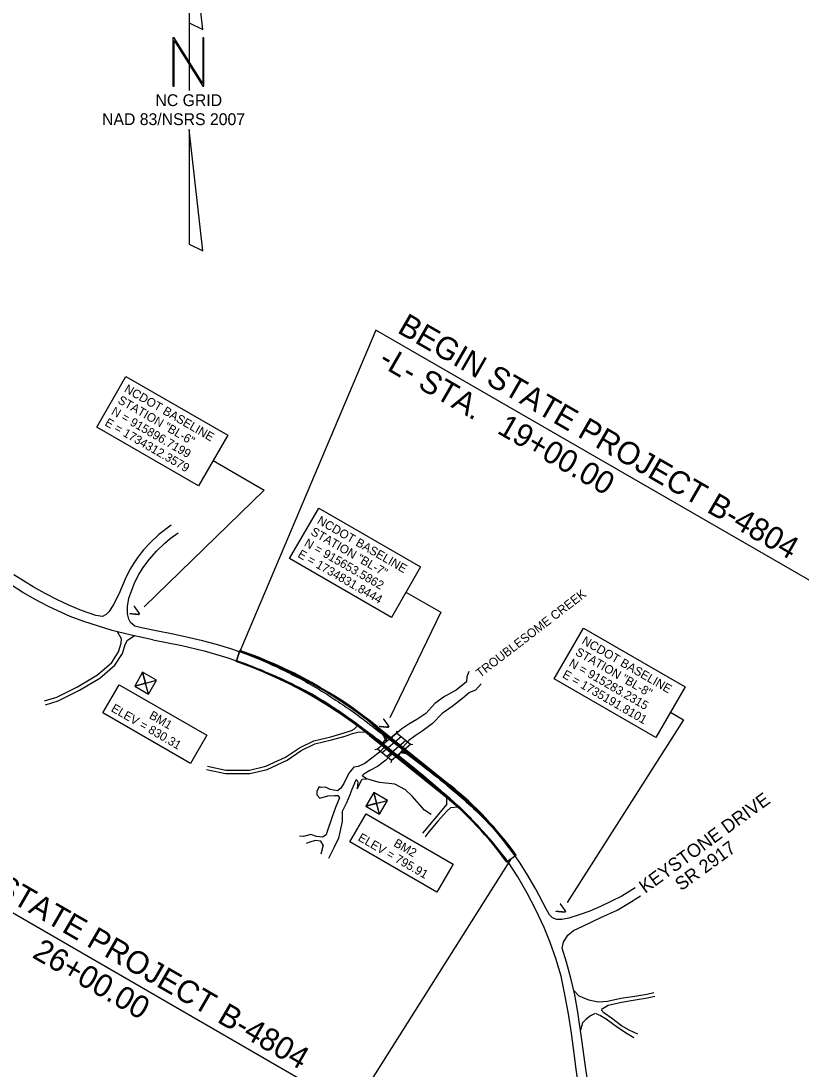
# Model space of a CAD drawing. Extents: x 1729269 to 1736953, y 913137 to 919486.
# Drawn here: x 1734090 to 1735676, y 914972 to 917102 of the extents above; entities that cross this region are included whole.
import ezdxf

# ---------------------------------------------------------------- set-up
doc = ezdxf.new("R2010")
doc.units = 0
for name, color, linetype in [('CTL North Arrow NAD 83 NSRS 2007 CELL', 7, 'Continuous'), ('CTL Sheet Text', 7, 'Continuous'), ('Default', 7, 'Continuous'), ('Exist Hydro Stream or Body of Water', 7, 'Continuous'), ('Exist Roads EOP', 7, 'Continuous'), ('Exist Roads Soil', 7, 'Continuous'), ('Exist Structure Major Deck Tunnel Box Culvert', 7, 'Continuous'), ('Old_Level_3', 7, 'Continuous'), ('Old_Level_57', 7, 'Continuous'), ('Proposed Right of Way Monument PSD Text', 7, 'Continuous')]:
    doc.layers.add(name, color=color, linetype=linetype)

# ---------------------------------------------------------------- blocks, each defined once
blk = doc.blocks.new('CTL NORTH ARROW NAD 83 NSRS 2007')
at = {"layer": 'Default'}
blk.add_line((0, 0), (0, 0), dxfattribs=at)
for points in [[(-0.003, 1.746), (-0.003, 0.579), (0.135, 0.511)], [(-0.168, -0.065), (-0.154, -0.065), (-0.154, 0.401), (0.135, -0.065), (0.148, -0.065), (0.148, 0.428), (0.135, 0.428), (0.135, -0.038), (-0.154, 0.428), (-0.168, 0.428)], [(-0.003, -1.671), (0.135, -1.739), (-0.003, -0.505)]]:
    blk.add_lwpolyline(points, close=True, dxfattribs=at)
blk.add_lwpolyline([(-0.003, 0.579), (-0.003, -0.107)], dxfattribs=at)
for s, p in [('NC GRID', (-0.345, -0.267)), ('NAD 83/NSRS 2007', (-0.888, -0.46))]:
    blk.add_text(s, height=0.12, dxfattribs=at).set_placement(p)

msp = doc.modelspace()

# ---------------------------------------------------------------- linework, layer by layer
at = {"layer": 'CTL Sheet Text'}
for p, q in [((1734811.2, 916473.9), (1734530.8, 915811.4)), ((1735762.6, 915924.6), (1734811.2, 916473.9)), ((1734764.2, 914889.5), (1733866.3, 915408)), ((1734764.2, 914889.5), (1735086.8, 915399.5))]:
    msp.add_line(p, q, dxfattribs=at)
at = {"layer": 'Default'}
for p, q in [((1734534, 915820.9), (1734527.5, 915801.9)), ((1734527.5, 915801.9), (1734534, 915820.9)), ((1734534, 915820.9), (1734534.7, 915822.7)), ((1734526.9, 915800.1), (1734527.5, 915801.9)), ((1734812.3, 915666.9), (1734960.6, 915547.4)), ((1734812.3, 915666.9), (1734960.6, 915547.4)), ((1734813.6, 915668.4), (1734961.9, 915549)), ((1734798.5, 915649.7), (1734946.8, 915530.3)), ((1734948.1, 915531.8), (1734799.8, 915651.3)), ((1734799.8, 915651.3), (1734948.1, 915531.8)), ((1734853, 915654.7), (1734814.6, 915621.9)), ((1734862.6, 915647), (1734824.1, 915614.3)), ((1734865.8, 915621.1), (1734834.2, 915645.7)), ((1734853, 915654.7), (1734854.2, 915659.3)), ((1734881.6, 915631.7), (1734853, 915654.7)), ((1734814.6, 915621.9), (1734809, 915621)), ((1734843.2, 915599), (1734814.6, 915621.9)), ((1734872.1, 915639.4), (1734833.6, 915606.6)), ((1734881.6, 915631.7), (1734843.2, 915599)), ((1734881.6, 915631.7), (1734886, 915632.5)), ((1734843.2, 915599), (1734841.5, 915594.5)), ((1735094.9, 915405.3), (1735078.7, 915393.7)), ((1735094.9, 915405.3), (1735078.7, 915393.7)), ((1735096.6, 915406.5), (1735094.9, 915405.3)), ((1735077.1, 915392.5), (1735078.7, 915393.7))]:
    msp.add_line(p, q, dxfattribs=at)
for points in [[(1734302.9, 916379.7), (1734509.9, 916260.2), (1734450.5, 916157.3), (1734243.5, 916276.9)], [(1734695, 916112.2), (1734902, 915992.7), (1734842.6, 915889.8), (1734635.6, 916009.3)], [(1735233.1, 915867.8), (1735439.7, 915748.5), (1735380.3, 915645.6), (1735173.7, 915764.9)], [(1734289.3, 915753.1), (1734467.5, 915650.3), (1734434.5, 915593.1), (1734256.3, 915696)], [(1734831.4, 915649), (1734832.9, 915637.5), (1734827.6, 915647.8), (1734829.9, 915647)], [(1734872.8, 915612.7), (1734861.4, 915614.5), (1734872.8, 915616.7), (1734871.4, 915614.7)], [(1734791.2, 915490.5), (1734968.2, 915388.4), (1734935.2, 915331.2), (1734758.2, 915433.4)]]:
    msp.add_lwpolyline(points, close=True, dxfattribs=at)
for points in [[(1734480.2, 916208.8), (1734584, 916148.8), (1734339.8, 915911.5)], [(1734872.3, 915941.3), (1734943.4, 915900.3), (1734839.3, 915685.7)], [(1735410, 915697), (1735436.7, 915681.6), (1735200.2, 915310.2)], [(1734865.8, 915621.1), (1734856.1, 915608.7), (1734824.7, 915633.5), (1734834.2, 915645.7)]]:
    msp.add_lwpolyline(points, dxfattribs=at)
for centre, radius, start, end in [((1734232, 914946.5), 925, 51.1452, 70.9432), ((1734232, 914946.5), 925, 51.1452, 70.9432), ((1734232, 914946.5), 927, 51.1452, 70.9432), ((1734232, 914946.5), 903, 51.1452, 70.9432), ((1734232, 914946.5), 905, 51.1452, 70.9432), ((1734232, 914946.5), 905, 51.1452, 70.9432), ((1734505.8, 914982.8), 725, 35.6458, 51.1452), ((1734505.8, 914982.8), 725, 35.6458, 51.1452), ((1734505.8, 914982.8), 727, 35.6458, 51.1452), ((1734505.8, 914982.8), 703, 35.6458, 51.1452), ((1734505.8, 914982.8), 705, 35.6458, 51.1452), ((1734505.8, 914982.8), 705, 35.6458, 51.1452)]:
    msp.add_arc(centre, radius, start, end, dxfattribs=at)
at = {"layer": 'Exist Hydro Stream or Body of Water'}
for points in [[(1735000.4, 915780.1), (1734996.3, 915769.1), (1734995.1, 915758.7), (1734974.1, 915741.8), (1734950.8, 915729), (1734930.8, 915714.9), (1734912.7, 915694.7), (1734894.6, 915682.3), (1734878, 915673.1), (1734864, 915663.1), (1734844.1, 915646.3), (1734840.1, 915641.3)], [(1735025.5, 915755.1), (1735013.8, 915742.3), (1735001.7, 915737.1), (1734987.9, 915725.5), (1734966.5, 915708.8), (1734946.2, 915694.3), (1734926.1, 915674.1), (1734907.3, 915660), (1734890.9, 915649), (1734878.2, 915640), (1734865.9, 915626), (1734862.5, 915623.7)], [(1734829.7, 915627.7), (1734818.6, 915616.3), (1734803.2, 915603.5), (1734789, 915592.7), (1734774.9, 915586.9), (1734766.1, 915585.3), (1734756.4, 915573.1), (1734745.7, 915552.1), (1734739.4, 915542.1)], [(1734847.9, 915613.6), (1734841.1, 915608.9), (1734831.2, 915599.4), (1734814.7, 915587.1), (1734798.9, 915578.8), (1734786.7, 915571.3), (1734783.1, 915567.8)], [(1734772.4, 915559.9), (1734769.7, 915557.9), (1734762.5, 915540.3), (1734758.5, 915529.5), (1734751.2, 915513.2), (1734742.9, 915495.6), (1734742.8, 915475.1), (1734735, 915441.4), (1734725.8, 915421.7), (1734715.1, 915399.6)], [(1734772.4, 915559.9), (1734774.2, 915556), (1734772.9, 915541.2), (1734783.4, 915561.2), (1734792.4, 915561.8), (1734783.1, 915567.8)], [(1734909.8, 915498.1), (1734884.9, 915526.8), (1734871.6, 915539.2), (1734849.9, 915550.9), (1734818.6, 915554.5), (1734792.4, 915561.8)], [(1734739.4, 915542.1), (1734732.8, 915537.7), (1734718.5, 915540.1), (1734709, 915544.8), (1734699.7, 915544.4), (1734696, 915545.5), (1734691.3, 915536.4), (1734691.4, 915529.3), (1734696.9, 915522.3), (1734713.4, 915527.1), (1734726.7, 915527.7), (1734733.8, 915527.9), (1734736.9, 915522.9)], [(1734736.9, 915523.3), (1734736.9, 915522.9), (1734729.3, 915503.3), (1734722.6, 915484.3), (1734711.2, 915452.5), (1734709.8, 915448)], [(1734923.6, 915489), (1734909.8, 915498.1)], [(1734709.8, 915448), (1734702.9, 915442.9), (1734690.2, 915444.4), (1734679.2, 915448.4), (1734664.3, 915444.6), (1734655.6, 915445.4)], [(1734703.8, 915426.7), (1734699.1, 915434.9), (1734687.5, 915436.3), (1734676.6, 915433.2), (1734669.1, 915430.6)], [(1734703.8, 915426.7), (1734699.1, 915408.7)]]:
    msp.add_lwpolyline(points, dxfattribs=at)
at = {"layer": 'Exist Roads EOP'}
for points in [[(1734394.7, 916077.1), (1734369.9, 916058.3), (1734352, 916041.7), (1734338.9, 916027.2), (1734327.3, 916012.3), (1734318.9, 916000.2), (1734311, 915987.6), (1734301.1, 915967.3), (1734288.4, 915937.1), (1734278, 915916.2), (1734269.2, 915901.9), (1734263.1, 915896.1), (1734255.2, 915892), (1734241.7, 915894), (1734212.5, 915904), (1734187.1, 915914.6), (1734163.6, 915925.7), (1734138.6, 915938.5), (1734114.2, 915952), (1734094.4, 915963.9), (1734074.8, 915976.6)], [(1734357.9, 915844.5), (1734311, 915854.6), (1734275.3, 915863.4), (1734247.5, 915872), (1734217.2, 915881.5), (1734189.8, 915891.8), (1734164.5, 915903.1), (1734143.9, 915913), (1734120.1, 915925.3), (1734093.2, 915940.8), (1734068, 915956.5), (1734040.6, 915976.2), (1734015.8, 915995.2), (1733991.1, 916015.8), (1733969, 916035.9), (1733954, 916050.6), (1733941.6, 916063.3)], [(1734367.8, 915861.9), (1734334.4, 915868.6), (1734321.3, 915872.1), (1734312.5, 915879.3), (1734309, 915886.6), (1734306.5, 915897.4), (1734306.4, 915912.3), (1734309.2, 915929.3), (1734314.9, 915945.5), (1734321, 915961.8), (1734328.9, 915976.9), (1734338, 915991), (1734350.9, 916008.6), (1734365.8, 916025), (1734381.9, 916040.7), (1734393.1, 916050.5), (1734409.2, 916061.5)], [(1734806.6, 915670.5), (1734794.2, 915681), (1734768.3, 915699.8), (1734740.3, 915718.7), (1734708.5, 915739.1), (1734678.6, 915756.5), (1734644.4, 915773.4), (1734606.7, 915791.5), (1734576.2, 915804.2), (1734547.7, 915815.2), (1734516.3, 915826.2), (1734487.1, 915834.9), (1734458.4, 915842.5), (1734423.7, 915850.6), (1734395.8, 915856.4), (1734367.8, 915861.9)], [(1734357.9, 915844.5), (1734416.4, 915832.9), (1734461.9, 915821.8), (1734507.9, 915808.5), (1734539.6, 915797.8), (1734580.6, 915781.2), (1734628, 915760.4), (1734664.3, 915740.2), (1734703.6, 915717.9), (1734746.1, 915690.1), (1734777, 915667.9)], [(1734777, 915667.9), (1734823.7, 915632.9)], [(1734806.6, 915670.5), (1734823.8, 915654.7), (1734834, 915645.7)], [(1734866.7, 915620.1), (1734865.5, 915621)], [(1735092, 915407.8), (1735070.9, 915436.3), (1735050.3, 915461.3), (1735020.8, 915492), (1734998.4, 915513.9), (1734970.6, 915538.4), (1734932.1, 915569.9), (1734898.2, 915597.2), (1734866.7, 915620.1)], [(1734944.8, 915533.6), (1734856.3, 915608.2)], [(1734944.8, 915533.6), (1734977.7, 915504.8), (1735009.1, 915475.9), (1735029.4, 915454.3), (1735050.5, 915429.9), (1735075.9, 915397.9)], [(1735338, 915340.4), (1735310.9, 915323.6), (1735288.9, 915312.4), (1735268.1, 915302.2), (1735246.3, 915292.5), (1735224.1, 915285), (1735203.5, 915278.4), (1735188.9, 915275.6), (1735179.1, 915275.8), (1735170.3, 915279.5), (1735164.1, 915285.3), (1735157.3, 915297.4), (1735136.6, 915337.4), (1735118, 915368.6), (1735102.9, 915392.3), (1735092, 915407.8)], [(1735242.5, 914819.2), (1735236, 914850.6), (1735229.7, 914892.9), (1735224.3, 914929.5), (1735218.2, 914971.6), (1735214, 915003.7), (1735208.6, 915044.9), (1735202.9, 915083.8), (1735195.5, 915123.4), (1735187.7, 915160.5), (1735177.1, 915196.8), (1735165.8, 915229.4), (1735153.3, 915259.8), (1735135.8, 915296.9), (1735118.8, 915329.6), (1735099.9, 915362.6), (1735080.5, 915391.6), (1735075.9, 915397.9)], [(1735190.1, 915217.8), (1735192.4, 915229.9), (1735201.2, 915244), (1735212.7, 915253.7), (1735232, 915262.2), (1735268.8, 915279.7), (1735301.6, 915294.7), (1735325.5, 915308.7), (1735349.4, 915324)], [(1735260.6, 914824.7), (1735254.7, 914857), (1735249.1, 914892.7), (1735242.4, 914939.7), (1735236, 914986.4), (1735230.7, 915026.7), (1735221.6, 915087.2), (1735215.3, 915122.6), (1735207.4, 915156.6), (1735198.8, 915189.4), (1735190.1, 915217.8)]]:
    msp.add_lwpolyline(points, dxfattribs=at)
at = {"layer": 'Exist Roads Soil'}
for points in [[(1734293.4, 915837.2), (1734294, 915846.6), (1734285.6, 915860.8)], [(1734301.2, 915834.9), (1734306.1, 915843.6), (1734319.7, 915852.7)], [(1734137.1, 915720), (1734162.2, 915728), (1734204.8, 915749), (1734245, 915773.2), (1734274, 915798.4), (1734288.2, 915819.9), (1734293.4, 915837.2)], [(1734139.5, 915712.2), (1734165.3, 915720.4), (1734208.8, 915741.8), (1734249.8, 915766.5), (1734280.2, 915792.9), (1734295.7, 915816.4), (1734301.2, 915834.9)], [(1734761.5, 915660.2), (1734767.6, 915663.5), (1734773.5, 915669.8)], [(1734467.1, 915580.6), (1734505.7, 915572.8), (1734554.7, 915572.6), (1734589.9, 915580.8), (1734630.6, 915599.8), (1734659.3, 915619.1), (1734687.1, 915632.8), (1734721.1, 915640.7), (1734748.8, 915648.7), (1734763.7, 915653.9)], [(1734468.5, 915587.2), (1734506.4, 915579.5), (1734553.9, 915579.3), (1734587.7, 915587.2), (1734627.3, 915605.6), (1734655.9, 915624.9), (1734684.8, 915639.2), (1734719.4, 915647.2), (1734746.8, 915655.1), (1734761.5, 915660.2)], [(1734763.7, 915653.9), (1734774.7, 915656.9), (1734789.8, 915657.6)], [(1734955.7, 915510.2), (1734955.7, 915518), (1734955.3, 915524.4)], [(1734955.7, 915510.2), (1734930.8, 915481), (1734909.7, 915455.9), (1734905.9, 915451)], [(1734955.2, 915496.3), (1734937.4, 915475.5), (1734916.4, 915450.5), (1734911, 915443.7)], [(1734955.2, 915496.3), (1734963.6, 915503.2), (1734977.8, 915504.7)], [(1735281.8, 915108.9), (1735263.1, 915107.9), (1735244.4, 915112), (1735230.9, 915117.6), (1735224.4, 915120.3), (1735213.1, 915131.9)], [(1735376.3, 915126.7), (1735362, 915123.2), (1735337.3, 915119.5), (1735309, 915115), (1735281.8, 915108.9)], [(1735378.1, 915119.1), (1735363.5, 915115.6), (1735338.5, 915111.8), (1735310.4, 915107.3), (1735283.5, 915101.3)], [(1735343.5, 915042.8), (1735326.3, 915050.8), (1735310.7, 915059.7), (1735290.2, 915075), (1735274.9, 915086), (1735269, 915092.1)], [(1735283.5, 915101.3), (1735269.6, 915092.6)], [(1735256.8, 915085.1), (1735247.7, 915079.8), (1735237.8, 915072.8), (1735231, 915065.8), (1735227.1, 915050.9)], [(1735258.2, 915084.5), (1735267.8, 915080.5), (1735279.3, 915074), (1735302.1, 915057.1), (1735322, 915043.9), (1735335.9, 915035.8)]]:
    msp.add_lwpolyline(points, dxfattribs=at)
at = {"layer": 'Exist Structure Major Deck Tunnel Box Culvert'}
msp.add_lwpolyline([(1734855.7, 915607.7), (1734823.4, 915632.5), (1734834.2, 915646), (1734865.6, 915621.3), (1734855.7, 915607.7)], dxfattribs=at)
at = {"layer": 'Old_Level_3'}
for points in [[(1734543.6, 915817), (1734596.7, 915795.1), (1734643.1, 915772.7), (1734683.1, 915750.9), (1734729.8, 915721.6), (1734764.7, 915698), (1734803.6, 915668.7), (1734832.5, 915645.7)], [(1734549.9, 915794.3), (1734589.6, 915778.2), (1734633.6, 915758.4), (1734673.1, 915738.4), (1734721.2, 915709.8), (1734758.5, 915684.1), (1734794.6, 915657.6), (1734825.3, 915634.6)], [(1734865.8, 915619.4), (1734899.8, 915592.9), (1734931, 915568.7), (1734948.4, 915554.7), (1734979.8, 915528.3), (1735019.6, 915492), (1735051.5, 915459.1), (1735067.6, 915441.5)], [(1734865.8, 915619.4), (1734899.8, 915592.9), (1734931, 915568.7), (1734948.4, 915554.7), (1734979.8, 915528.3), (1735019.6, 915492), (1735051.5, 915459.1), (1735067.6, 915441.5)], [(1734858, 915608.9), (1734899.1, 915575.6), (1734937, 915543.4), (1734973.3, 915511.8), (1735003.9, 915482.3)], [(1734858, 915608.9), (1734899.1, 915575.6), (1734937, 915543.4), (1734973.3, 915511.8), (1735003.9, 915482.3)]]:
    msp.add_spline(points, degree=3, dxfattribs=at)
at = {"layer": 'Old_Level_57'}
for p, q in [((1734348.9, 915734), (1734337, 915778.3)), ((1734320.8, 915750.2), (1734365.1, 915762.1)), ((1734818.5, 915489.9), (1734806.7, 915534.2)), ((1734790.4, 915506.1), (1734834.7, 915518))]:
    msp.add_line(p, q, dxfattribs=at)
for points in [[(1734365.1, 915762.1), (1734337, 915778.3), (1734320.8, 915750.2), (1734348.9, 915734)], [(1734834.7, 915518), (1734806.7, 915534.2), (1734790.4, 915506.1), (1734818.5, 915489.9)]]:
    msp.add_lwpolyline(points, close=True, dxfattribs=at)
for points in [[(1734343, 915756.1), (1734365.1, 915762.1), (1734337, 915778.3), (1734343, 915756.1)], [(1734343, 915756.1), (1734320.8, 915750.2), (1734348.9, 915734), (1734343, 915756.1)], [(1734812.6, 915512), (1734834.7, 915518), (1734806.7, 915534.2), (1734812.6, 915512)], [(1734812.6, 915512), (1734790.4, 915506.1), (1734818.5, 915489.9), (1734812.6, 915512)]]:
    msp.add_lwpolyline(points, dxfattribs=at)

# ---------------------------------------------------------------- block references
at = {"layer": 'CTL North Arrow NAD 83 NSRS 2007 CELL', "xscale": 200.00000000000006, "yscale": 200.00000000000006}
msp.add_blockref('CTL NORTH ARROW NAD 83 NSRS 2007', (1734432, 916982.6), dxfattribs=at)

# ---------------------------------------------------------------- texts
at = {"layer": 'CTL Sheet Text'}
for s, height, p in [('BEGIN STATE PROJECT ', 45.911, (1734852.6, 916470)), ('-L- STA. ', 45.91, (1734814.3, 916403.7)), ('19+00.00', 45.91, (1735055.4, 916265.7)), ('B-4804', 45.91, (1735481.7, 916105.3)), ('END STATE PROJECT ', 45.911, (1733907.6, 915404)), ('26+00.00', 45.91, (1734110.4, 915199.7)), ('B-4804', 45.91, (1734486.2, 915068.5))]:
    msp.add_text(s, height=height, rotation=330, dxfattribs=at).set_placement(p)
at = {"layer": 'Default'}
msp.add_text('TROUBLESOME CREEK', height=18, rotation=37.5535, dxfattribs=at).set_placement((1735023.1, 915766.8))
at = {"layer": 'Exist Roads EOP'}
for s, p in [('KEYSTONE DRIVE', (1735358.6, 915327.9)), ('SR 2917', (1735431.7, 915333))]:
    msp.add_text(s, height=27, rotation=35.9613, dxfattribs=at).set_placement(p)
at = {"layer": 'Old_Level_57'}
for p in [(1734306.3, 915894.5), (1734813.4, 915665.2), (1735172.6, 915289.5)]:
    msp.add_text('>', height=28.7, rotation=330.0142, dxfattribs=at).set_placement(p)
at = {"layer": 'Proposed Right of Way Monument PSD Text'}
for s, p in [('NCDOT BASELINE', (1734298.1, 916349.5)), ('STATION "BL-6"', (1734284.9, 916326.6)), ('N = 915896.7199', (1734271.7, 916303.7)), ('E = 1734312.3579', (1734258.5, 916280.9)), ('NCDOT BASELINE', (1734690.3, 916082)), ('STATION "BL-7"', (1734677.1, 916059.1)), ('N = 915653.5862', (1734663.9, 916036.2)), ('E = 1734831.8444', (1734650.7, 916013.4)), ('NCDOT BASELINE', (1735228.3, 915837.5)), ('STATION "BL-8"', (1735215.1, 915814.6)), ('N = 915283.2315', (1735201.9, 915791.8)), ('E = 1735191.8101', (1735188.7, 915768.9)), ('ELEV = 830.31', (1734271.3, 915700)), ('BM1', (1734348.7, 915685.8)), ('ELEV = 795.91', (1734773.2, 915437.4)), ('BM2', (1734845.7, 915426))]:
    msp.add_text(s, height=17.6, rotation=330, dxfattribs=at).set_placement(p)

doc.saveas('drawing.dxf')
